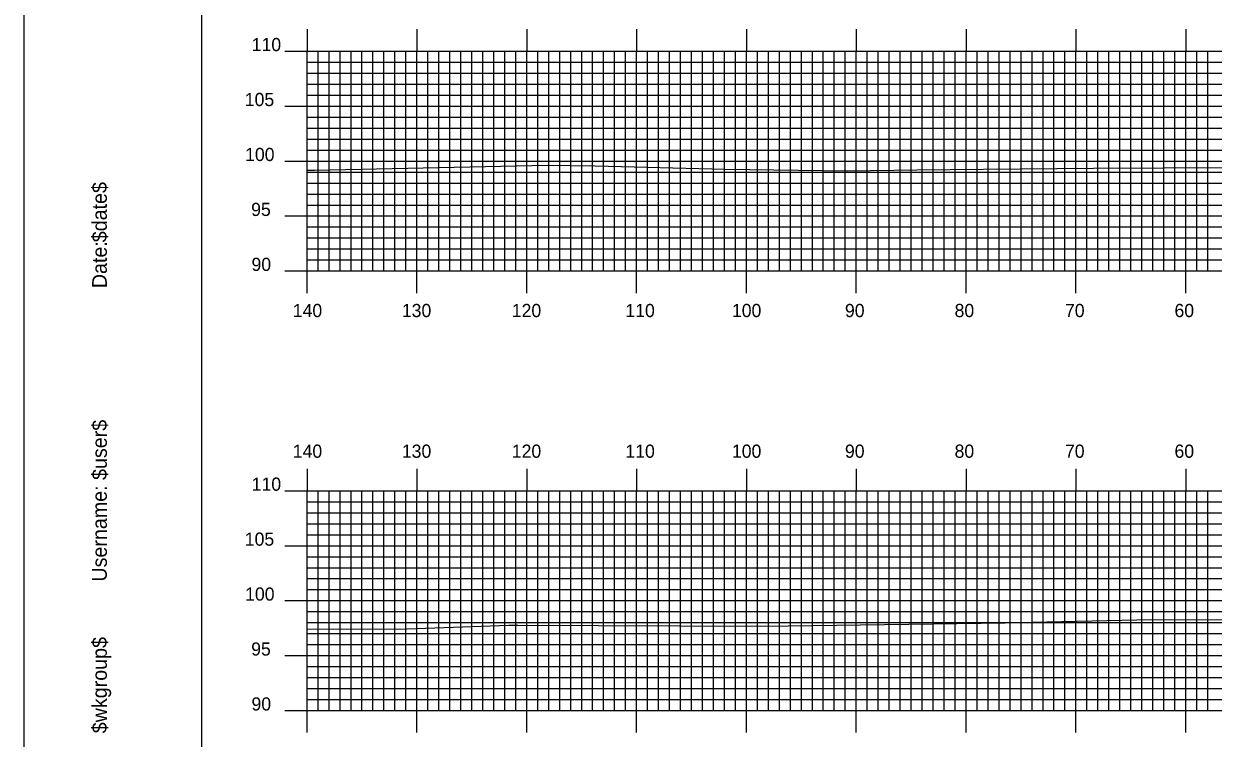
# Model space of a CAD drawing. Extents: x 1778712 to 1779055, y 442591 to 442811.
# Drawn here: x 1778712 to 1778820.3, y 442686.2 to 442751.2 of the extents above; entities that cross this region are included whole.
import ezdxf

# ---------------------------------------------------------------- set-up
doc = ezdxf.new("R2010")
doc.units = 0
for name, color, linetype in [('BORDER', 7, 'Continuous'), ('H_V ANNOTATION', 7, 'Continuous'), ('MAJOR', 7, 'Continuous'), ('MINOR', 7, 'Continuous'), ('PLOT BOUNDARY', 7, 'Continuous'), ('S_Roadway_Centerline', 7, 'Continuous')]:
    doc.layers.add(name, color=color, linetype=linetype)

msp = doc.modelspace()

# ---------------------------------------------------------------- linework, layer by layer
at = {"layer": 'BORDER'}
msp.add_lwpolyline([(1778728.22, 442596.67), (1779048.22, 442596.67), (1779048.22, 442806.67), (1778728.22, 442806.67)], close=True, dxfattribs=at)
at = {"layer": 'MAJOR'}
for p, q in [((1778737.82, 442750.67), (1778737.82, 442748.67)), ((1778747.82, 442750.67), (1778747.82, 442748.67)), ((1778757.82, 442750.67), (1778757.82, 442748.67)), ((1778767.82, 442750.67), (1778767.82, 442748.67)), ((1778777.82, 442750.67), (1778777.82, 442748.67)), ((1778787.82, 442750.67), (1778787.82, 442748.67)), ((1778797.82, 442750.67), (1778797.82, 442748.67)), ((1778807.82, 442750.67), (1778807.82, 442748.67)), ((1778817.82, 442750.67), (1778817.82, 442748.67)), ((1778735.81, 442748.67), (1778737.82, 442748.67)), ((1778737.82, 442748.67), (1779017.82, 442748.67)), ((1778737.82, 442728.67), (1778737.82, 442748.67)), ((1778737.82, 442728.67), (1778737.82, 442748.67)), ((1778737.82, 442748.67), (1779017.82, 442748.67)), ((1778747.82, 442728.67), (1778747.82, 442748.67)), ((1778757.82, 442728.67), (1778757.82, 442748.67)), ((1778767.82, 442728.67), (1778767.82, 442748.67)), ((1778777.82, 442728.67), (1778777.82, 442748.67)), ((1778787.82, 442728.67), (1778787.82, 442748.67)), ((1778797.82, 442728.67), (1778797.82, 442748.67)), ((1778807.82, 442728.67), (1778807.82, 442748.67)), ((1778817.82, 442728.67), (1778817.82, 442748.67)), ((1778735.81, 442743.67), (1778737.82, 442743.67)), ((1778737.82, 442743.67), (1779017.82, 442743.67)), ((1778735.81, 442738.67), (1778737.82, 442738.67)), ((1778737.82, 442738.67), (1779017.82, 442738.67)), ((1778735.81, 442733.67), (1778737.82, 442733.67)), ((1778737.82, 442733.67), (1779017.82, 442733.67)), ((1778735.81, 442728.67), (1778737.82, 442728.67)), ((1778737.82, 442728.67), (1779017.82, 442728.67)), ((1778737.82, 442728.67), (1779017.82, 442728.67)), ((1778737.82, 442726.66), (1778737.82, 442728.67)), ((1778747.82, 442726.66), (1778747.82, 442728.67)), ((1778757.82, 442726.66), (1778757.82, 442728.67)), ((1778767.82, 442726.66), (1778767.82, 442728.67)), ((1778777.82, 442726.66), (1778777.82, 442728.67)), ((1778787.82, 442726.66), (1778787.82, 442728.67)), ((1778797.82, 442726.66), (1778797.82, 442728.67)), ((1778807.82, 442726.66), (1778807.82, 442728.67)), ((1778817.82, 442726.66), (1778817.82, 442728.67)), ((1778737.82, 442710.67), (1778737.82, 442708.67)), ((1778747.82, 442710.67), (1778747.82, 442708.67)), ((1778757.82, 442710.67), (1778757.82, 442708.67)), ((1778767.82, 442710.67), (1778767.82, 442708.67)), ((1778777.82, 442710.67), (1778777.82, 442708.67)), ((1778787.82, 442710.67), (1778787.82, 442708.67)), ((1778797.82, 442710.67), (1778797.82, 442708.67)), ((1778807.82, 442710.67), (1778807.82, 442708.67)), ((1778817.82, 442710.67), (1778817.82, 442708.67)), ((1778735.81, 442708.67), (1778737.82, 442708.67)), ((1778737.82, 442708.67), (1779017.82, 442708.67)), ((1778737.82, 442688.67), (1778737.82, 442708.67)), ((1778737.82, 442688.67), (1778737.82, 442708.67)), ((1778737.82, 442708.67), (1779017.82, 442708.67)), ((1778747.82, 442688.67), (1778747.82, 442708.67)), ((1778757.82, 442688.67), (1778757.82, 442708.67)), ((1778767.82, 442688.67), (1778767.82, 442708.67)), ((1778777.82, 442688.67), (1778777.82, 442708.67)), ((1778787.82, 442688.67), (1778787.82, 442708.67)), ((1778797.82, 442688.67), (1778797.82, 442708.67)), ((1778807.82, 442688.67), (1778807.82, 442708.67)), ((1778817.82, 442688.67), (1778817.82, 442708.67)), ((1778735.81, 442703.67), (1778737.82, 442703.67)), ((1778737.82, 442703.67), (1779017.82, 442703.67)), ((1778735.81, 442698.67), (1778737.82, 442698.67)), ((1778737.82, 442698.67), (1779017.82, 442698.67)), ((1778735.81, 442693.67), (1778737.82, 442693.67)), ((1778737.82, 442693.67), (1779017.82, 442693.67)), ((1778735.81, 442688.67), (1778737.82, 442688.67)), ((1778737.82, 442688.67), (1779017.82, 442688.67)), ((1778737.82, 442688.67), (1779017.82, 442688.67)), ((1778737.82, 442686.66), (1778737.82, 442688.67)), ((1778747.82, 442686.66), (1778747.82, 442688.67)), ((1778757.82, 442686.66), (1778757.82, 442688.67)), ((1778767.82, 442686.66), (1778767.82, 442688.67)), ((1778777.82, 442686.66), (1778777.82, 442688.67)), ((1778787.82, 442686.66), (1778787.82, 442688.67)), ((1778797.82, 442686.66), (1778797.82, 442688.67)), ((1778807.82, 442686.66), (1778807.82, 442688.67)), ((1778817.82, 442686.66), (1778817.82, 442688.67))]:
    msp.add_line(p, q, dxfattribs=at)
at = {"layer": 'MINOR'}
for p, q in [((1778738.82, 442728.67), (1778738.82, 442748.67)), ((1778739.82, 442728.67), (1778739.82, 442748.67)), ((1778740.82, 442728.67), (1778740.82, 442748.67)), ((1778741.82, 442728.67), (1778741.82, 442748.67)), ((1778742.82, 442728.67), (1778742.82, 442748.67)), ((1778743.82, 442728.67), (1778743.82, 442748.67)), ((1778744.82, 442728.67), (1778744.82, 442748.67)), ((1778745.82, 442728.67), (1778745.82, 442748.67)), ((1778746.82, 442728.67), (1778746.82, 442748.67)), ((1778748.82, 442728.67), (1778748.82, 442748.67)), ((1778749.82, 442728.67), (1778749.82, 442748.67)), ((1778750.82, 442728.67), (1778750.82, 442748.67)), ((1778751.82, 442728.67), (1778751.82, 442748.67)), ((1778752.82, 442728.67), (1778752.82, 442748.67)), ((1778753.82, 442728.67), (1778753.82, 442748.67)), ((1778754.82, 442728.67), (1778754.82, 442748.67)), ((1778755.82, 442728.67), (1778755.82, 442748.67)), ((1778756.82, 442728.67), (1778756.82, 442748.67)), ((1778758.82, 442728.67), (1778758.82, 442748.67)), ((1778759.82, 442728.67), (1778759.82, 442748.67)), ((1778760.82, 442728.67), (1778760.82, 442748.67)), ((1778761.82, 442728.67), (1778761.82, 442748.67)), ((1778762.82, 442728.67), (1778762.82, 442748.67)), ((1778763.82, 442728.67), (1778763.82, 442748.67)), ((1778764.82, 442728.67), (1778764.82, 442748.67)), ((1778765.82, 442728.67), (1778765.82, 442748.67)), ((1778766.82, 442728.67), (1778766.82, 442748.67)), ((1778768.82, 442728.67), (1778768.82, 442748.67)), ((1778769.82, 442728.67), (1778769.82, 442748.67)), ((1778770.82, 442728.67), (1778770.82, 442748.67)), ((1778771.82, 442728.67), (1778771.82, 442748.67)), ((1778772.82, 442728.67), (1778772.82, 442748.67)), ((1778773.82, 442728.67), (1778773.82, 442748.67)), ((1778774.82, 442728.67), (1778774.82, 442748.67)), ((1778775.82, 442728.67), (1778775.82, 442748.67)), ((1778776.82, 442728.67), (1778776.82, 442748.67)), ((1778778.82, 442728.67), (1778778.82, 442748.67)), ((1778779.82, 442728.67), (1778779.82, 442748.67)), ((1778780.82, 442728.67), (1778780.82, 442748.67)), ((1778781.82, 442728.67), (1778781.82, 442748.67)), ((1778782.82, 442728.67), (1778782.82, 442748.67)), ((1778783.82, 442728.67), (1778783.82, 442748.67)), ((1778784.82, 442728.67), (1778784.82, 442748.67)), ((1778785.82, 442728.67), (1778785.82, 442748.67)), ((1778786.82, 442728.67), (1778786.82, 442748.67)), ((1778788.82, 442728.67), (1778788.82, 442748.67)), ((1778789.82, 442728.67), (1778789.82, 442748.67)), ((1778790.82, 442728.67), (1778790.82, 442748.67)), ((1778791.82, 442728.67), (1778791.82, 442748.67)), ((1778792.82, 442728.67), (1778792.82, 442748.67)), ((1778793.82, 442728.67), (1778793.82, 442748.67)), ((1778794.82, 442728.67), (1778794.82, 442748.67)), ((1778795.82, 442728.67), (1778795.82, 442748.67)), ((1778796.82, 442728.67), (1778796.82, 442748.67)), ((1778798.82, 442728.67), (1778798.82, 442748.67)), ((1778799.82, 442728.67), (1778799.82, 442748.67)), ((1778800.82, 442728.67), (1778800.82, 442748.67)), ((1778801.82, 442728.67), (1778801.82, 442748.67)), ((1778802.82, 442728.67), (1778802.82, 442748.67)), ((1778803.82, 442728.67), (1778803.82, 442748.67)), ((1778804.82, 442728.67), (1778804.82, 442748.67)), ((1778805.82, 442728.67), (1778805.82, 442748.67)), ((1778806.82, 442728.67), (1778806.82, 442748.67)), ((1778808.82, 442728.67), (1778808.82, 442748.67)), ((1778809.82, 442728.67), (1778809.82, 442748.67)), ((1778810.82, 442728.67), (1778810.82, 442748.67)), ((1778811.82, 442728.67), (1778811.82, 442748.67)), ((1778812.82, 442728.67), (1778812.82, 442748.67)), ((1778813.82, 442728.67), (1778813.82, 442748.67)), ((1778814.82, 442728.67), (1778814.82, 442748.67)), ((1778815.82, 442728.67), (1778815.82, 442748.67)), ((1778816.82, 442728.67), (1778816.82, 442748.67)), ((1778818.82, 442728.67), (1778818.82, 442748.67)), ((1778819.82, 442728.67), (1778819.82, 442748.67)), ((1778737.82, 442747.67), (1779017.82, 442747.67)), ((1778737.82, 442747.67), (1778739.82, 442747.67)), ((1778737.82, 442746.67), (1779017.82, 442746.67)), ((1778737.82, 442746.67), (1778739.82, 442746.67)), ((1778737.82, 442745.67), (1779017.82, 442745.67)), ((1778737.82, 442745.67), (1778739.82, 442745.67)), ((1778737.82, 442744.67), (1779017.82, 442744.67)), ((1778737.82, 442744.67), (1778739.82, 442744.67)), ((1778737.82, 442742.67), (1779017.82, 442742.67)), ((1778737.82, 442742.67), (1778739.82, 442742.67)), ((1778737.82, 442741.67), (1779017.82, 442741.67)), ((1778737.82, 442741.67), (1778739.82, 442741.67)), ((1778737.82, 442740.67), (1779017.82, 442740.67)), ((1778737.82, 442740.67), (1778739.82, 442740.67)), ((1778737.82, 442739.67), (1779017.82, 442739.67)), ((1778737.82, 442739.67), (1778739.82, 442739.67)), ((1778737.82, 442737.67), (1779017.82, 442737.67)), ((1778737.82, 442737.67), (1778739.82, 442737.67)), ((1778737.82, 442736.67), (1779017.82, 442736.67)), ((1778737.82, 442736.67), (1778739.82, 442736.67)), ((1778737.82, 442735.67), (1779017.82, 442735.67)), ((1778737.82, 442735.67), (1778739.82, 442735.67)), ((1778737.82, 442734.67), (1779017.82, 442734.67)), ((1778737.82, 442734.67), (1778739.82, 442734.67)), ((1778737.82, 442732.67), (1779017.82, 442732.67)), ((1778737.82, 442732.67), (1778739.82, 442732.67)), ((1778737.82, 442731.67), (1779017.82, 442731.67)), ((1778737.82, 442731.67), (1778739.82, 442731.67)), ((1778737.82, 442730.67), (1779017.82, 442730.67)), ((1778737.82, 442730.67), (1778739.82, 442730.67)), ((1778737.82, 442729.67), (1779017.82, 442729.67)), ((1778737.82, 442729.67), (1778739.82, 442729.67)), ((1778738.82, 442688.67), (1778738.82, 442708.67)), ((1778739.82, 442688.67), (1778739.82, 442708.67)), ((1778740.82, 442688.67), (1778740.82, 442708.67)), ((1778741.82, 442688.67), (1778741.82, 442708.67)), ((1778742.82, 442688.67), (1778742.82, 442708.67)), ((1778743.82, 442688.67), (1778743.82, 442708.67)), ((1778744.82, 442688.67), (1778744.82, 442708.67)), ((1778745.82, 442688.67), (1778745.82, 442708.67)), ((1778746.82, 442688.67), (1778746.82, 442708.67)), ((1778748.82, 442688.67), (1778748.82, 442708.67)), ((1778749.82, 442688.67), (1778749.82, 442708.67)), ((1778750.82, 442688.67), (1778750.82, 442708.67)), ((1778751.82, 442688.67), (1778751.82, 442708.67)), ((1778752.82, 442688.67), (1778752.82, 442708.67)), ((1778753.82, 442688.67), (1778753.82, 442708.67)), ((1778754.82, 442688.67), (1778754.82, 442708.67)), ((1778755.82, 442688.67), (1778755.82, 442708.67)), ((1778756.82, 442688.67), (1778756.82, 442708.67)), ((1778758.82, 442688.67), (1778758.82, 442708.67)), ((1778759.82, 442688.67), (1778759.82, 442708.67)), ((1778760.82, 442688.67), (1778760.82, 442708.67)), ((1778761.82, 442688.67), (1778761.82, 442708.67)), ((1778762.82, 442688.67), (1778762.82, 442708.67)), ((1778763.82, 442688.67), (1778763.82, 442708.67)), ((1778764.82, 442688.67), (1778764.82, 442708.67)), ((1778765.82, 442688.67), (1778765.82, 442708.67)), ((1778766.82, 442688.67), (1778766.82, 442708.67)), ((1778768.82, 442688.67), (1778768.82, 442708.67)), ((1778769.82, 442688.67), (1778769.82, 442708.67)), ((1778770.82, 442688.67), (1778770.82, 442708.67)), ((1778771.82, 442688.67), (1778771.82, 442708.67)), ((1778772.82, 442688.67), (1778772.82, 442708.67)), ((1778773.82, 442688.67), (1778773.82, 442708.67)), ((1778774.82, 442688.67), (1778774.82, 442708.67)), ((1778775.82, 442688.67), (1778775.82, 442708.67)), ((1778776.82, 442688.67), (1778776.82, 442708.67)), ((1778778.82, 442688.67), (1778778.82, 442708.67)), ((1778779.82, 442688.67), (1778779.82, 442708.67)), ((1778780.82, 442688.67), (1778780.82, 442708.67)), ((1778781.82, 442688.67), (1778781.82, 442708.67)), ((1778782.82, 442688.67), (1778782.82, 442708.67)), ((1778783.82, 442688.67), (1778783.82, 442708.67)), ((1778784.82, 442688.67), (1778784.82, 442708.67)), ((1778785.82, 442688.67), (1778785.82, 442708.67)), ((1778786.82, 442688.67), (1778786.82, 442708.67)), ((1778788.82, 442688.67), (1778788.82, 442708.67)), ((1778789.82, 442688.67), (1778789.82, 442708.67)), ((1778790.82, 442688.67), (1778790.82, 442708.67)), ((1778791.82, 442688.67), (1778791.82, 442708.67)), ((1778792.82, 442688.67), (1778792.82, 442708.67)), ((1778793.82, 442688.67), (1778793.82, 442708.67)), ((1778794.82, 442688.67), (1778794.82, 442708.67)), ((1778795.82, 442688.67), (1778795.82, 442708.67)), ((1778796.82, 442688.67), (1778796.82, 442708.67)), ((1778798.82, 442688.67), (1778798.82, 442708.67)), ((1778799.82, 442688.67), (1778799.82, 442708.67)), ((1778800.82, 442688.67), (1778800.82, 442708.67)), ((1778801.82, 442688.67), (1778801.82, 442708.67)), ((1778802.82, 442688.67), (1778802.82, 442708.67)), ((1778803.82, 442688.67), (1778803.82, 442708.67)), ((1778804.82, 442688.67), (1778804.82, 442708.67)), ((1778805.82, 442688.67), (1778805.82, 442708.67)), ((1778806.82, 442688.67), (1778806.82, 442708.67)), ((1778808.82, 442688.67), (1778808.82, 442708.67)), ((1778809.82, 442688.67), (1778809.82, 442708.67)), ((1778810.82, 442688.67), (1778810.82, 442708.67)), ((1778811.82, 442688.67), (1778811.82, 442708.67)), ((1778812.82, 442688.67), (1778812.82, 442708.67)), ((1778813.82, 442688.67), (1778813.82, 442708.67)), ((1778814.82, 442688.67), (1778814.82, 442708.67)), ((1778815.82, 442688.67), (1778815.82, 442708.67)), ((1778816.82, 442688.67), (1778816.82, 442708.67)), ((1778818.82, 442688.67), (1778818.82, 442708.67)), ((1778819.82, 442688.67), (1778819.82, 442708.67)), ((1778737.82, 442707.67), (1779017.82, 442707.67)), ((1778737.82, 442707.67), (1778739.82, 442707.67)), ((1778737.82, 442706.67), (1779017.82, 442706.67)), ((1778737.82, 442706.67), (1778739.82, 442706.67)), ((1778737.82, 442705.67), (1779017.82, 442705.67)), ((1778737.82, 442705.67), (1778739.82, 442705.67)), ((1778737.82, 442704.67), (1779017.82, 442704.67)), ((1778737.82, 442704.67), (1778739.82, 442704.67)), ((1778737.82, 442702.67), (1779017.82, 442702.67)), ((1778737.82, 442702.67), (1778739.82, 442702.67)), ((1778737.82, 442701.67), (1779017.82, 442701.67)), ((1778737.82, 442701.67), (1778739.82, 442701.67)), ((1778737.82, 442700.67), (1779017.82, 442700.67)), ((1778737.82, 442700.67), (1778739.82, 442700.67)), ((1778737.82, 442699.67), (1779017.82, 442699.67)), ((1778737.82, 442699.67), (1778739.82, 442699.67)), ((1778737.82, 442697.67), (1779017.82, 442697.67)), ((1778737.82, 442697.67), (1778739.82, 442697.67)), ((1778737.82, 442696.67), (1779017.82, 442696.67)), ((1778737.82, 442696.67), (1778739.82, 442696.67)), ((1778737.82, 442695.67), (1779017.82, 442695.67)), ((1778737.82, 442695.67), (1778739.82, 442695.67)), ((1778737.82, 442694.67), (1779017.82, 442694.67)), ((1778737.82, 442694.67), (1778739.82, 442694.67)), ((1778737.82, 442692.67), (1779017.82, 442692.67)), ((1778737.82, 442692.67), (1778739.82, 442692.67)), ((1778737.82, 442691.67), (1779017.82, 442691.67)), ((1778737.82, 442691.67), (1778739.82, 442691.67)), ((1778737.82, 442690.67), (1779017.82, 442690.67)), ((1778737.82, 442690.67), (1778739.82, 442690.67)), ((1778737.82, 442689.67), (1779017.82, 442689.67)), ((1778737.82, 442689.67), (1778739.82, 442689.67))]:
    msp.add_line(p, q, dxfattribs=at)
at = {"layer": 'PLOT BOUNDARY'}
msp.add_lwpolyline([(1778712.03, 442590.55), (1779052.03, 442590.55), (1779052.03, 442810.55), (1778712.03, 442810.55)], close=True, dxfattribs=at)
at = {"layer": 'S_Roadway_Centerline'}
for points in [[(1778737.82, 442737.83), (1778738.51, 442737.83), (1778759.72, 442738.29), (1778764.05, 442738.23), (1778775.85, 442737.94), (1778787.02, 442737.77), (1778793.34, 442737.88), (1778799.39, 442737.93), (1778809.41, 442738.01), (1778815.82, 442738.05), (1778821.89, 442738.09)], [(1778737.82, 442696.09), (1778746.07, 442696.06), (1778756.19, 442696.43), (1778757.02, 442696.43), (1778779.08, 442696.35), (1778781.61, 442696.38), (1778801.37, 442696.64), (1778805.18, 442696.73), (1778814.74, 442696.94), (1778824.28, 442696.92), (1778826.84, 442696.84), (1778829.09, 442696.85), (1778847.69, 442696.93), (1778850.23, 442696.96), (1778853.01, 442697.07), (1778860.8, 442697.39), (1778870.23, 442697.37), (1778876.08, 442697.31), (1778891.62, 442697.6), (1778900.58, 442697.8), (1778919.12, 442697.46), (1778923.55, 442697.44), (1778930.54, 442697.55)]]:
    msp.add_lwpolyline(points, dxfattribs=at)

# ---------------------------------------------------------------- texts
at = {"layer": 'BORDER'}
for s, p in [('$date$', (1778719.59, 442731.28)), ('Date:', (1778719.59, 442727.1)), ('$user$', (1778719.59, 442709.65)), ('Username:', (1778719.59, 442700.4)), ('$wkgroup$', (1778719.59, 442686.6))]:
    msp.add_text(s, height=1.339, rotation=90, dxfattribs=at).set_placement(p)
at = {"layer": 'H_V ANNOTATION'}
for s, p in [('110', (1778732.78, 442748.67)), ('105', (1778732.15, 442743.67)), ('100', (1778732.18, 442738.67)), ('95', (1778732.73, 442733.67)), ('90', (1778732.76, 442728.67)), ('140', (1778736.52, 442724.47)), ('130', (1778746.45, 442724.47)), ('120', (1778756.46, 442724.47)), ('110', (1778766.8, 442724.47)), ('100', (1778776.5, 442724.47)), ('90', (1778786.79, 442724.47)), ('80', (1778796.77, 442724.47)), ('70', (1778806.82, 442724.47)), ('60', (1778816.79, 442724.47)), ('140', (1778736.52, 442711.67)), ('130', (1778746.45, 442711.67)), ('120', (1778756.46, 442711.67)), ('110', (1778766.8, 442711.67)), ('100', (1778776.5, 442711.67)), ('90', (1778786.79, 442711.67)), ('80', (1778796.77, 442711.67)), ('70', (1778806.82, 442711.67)), ('60', (1778816.79, 442711.67)), ('110', (1778732.78, 442708.67)), ('105', (1778732.15, 442703.67)), ('100', (1778732.18, 442698.67)), ('95', (1778732.73, 442693.67)), ('90', (1778732.76, 442688.67))]:
    msp.add_text(s, height=1.2, dxfattribs=at).set_placement(p)
at = {"layer": 'MAJOR'}
for p in [(1778737.81, 442728.67), (1778737.81, 442688.67)]:
    msp.add_text('-', height=0.012, dxfattribs=at).set_placement(p)

doc.saveas('drawing.dxf')
